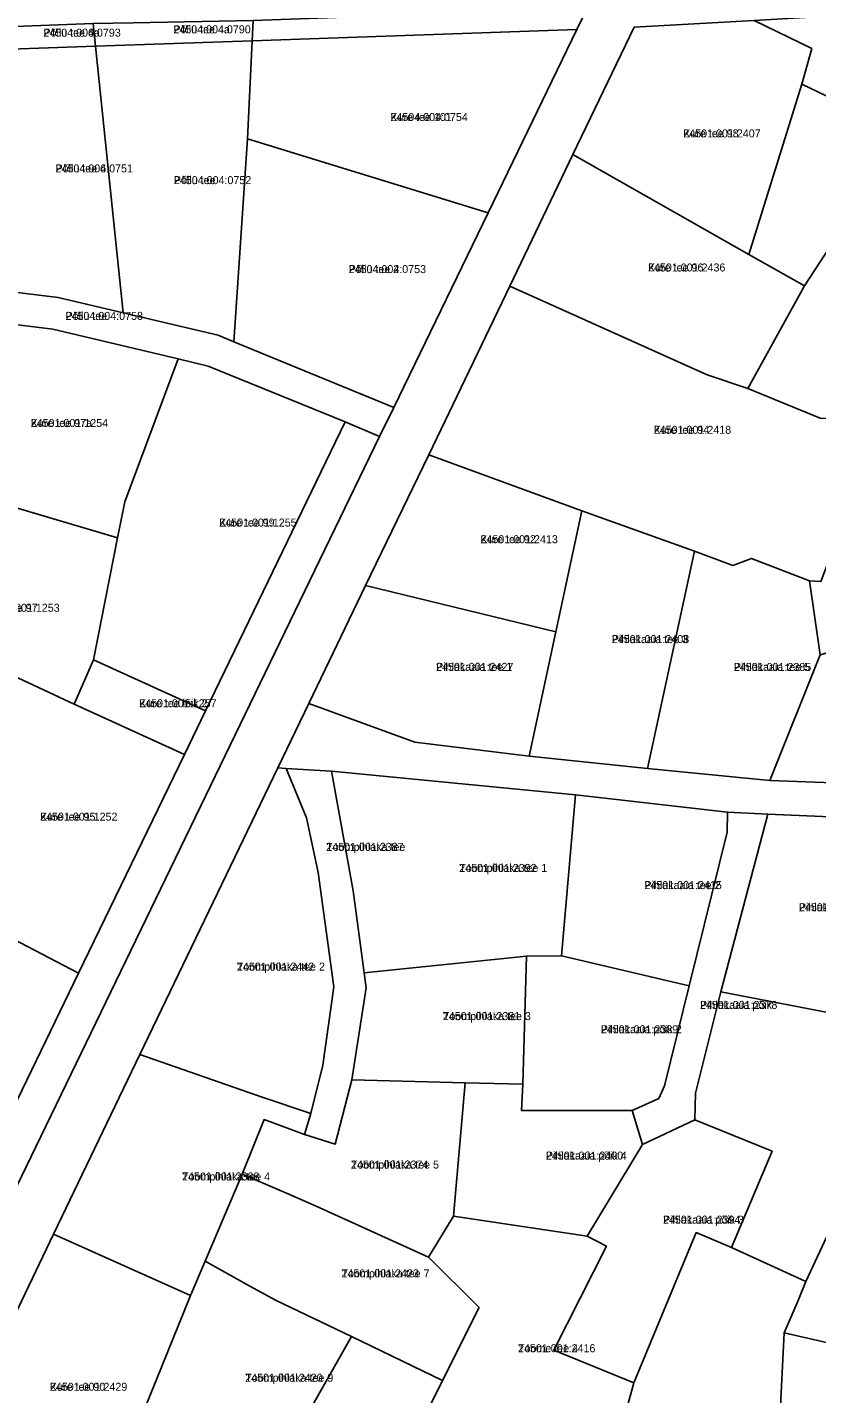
# Model space of a CAD drawing. Extents: x 551291 to 575799, y 6581704 to 6610137.
# Drawn here: x 559378.6 to 559526.5, y 6593957.3 to 6594213.3 of the extents above; entities that cross this region are included whole.
import ezdxf

# ---------------------------------------------------------------- set-up
doc = ezdxf.new("R2010")
doc.units = 0
for name, color, linetype in [('L_AADRESS', 7, 'Continuous'), ('PIIR', 7, 'Continuous'), ('TUNNUS', 7, 'Continuous')]:
    doc.layers.add(name, color=color, linetype=linetype)

msp = doc.modelspace()

# ---------------------------------------------------------------- linework, layer by layer
at = {"layer": 'PIIR'}
for points in [[(559525.57, 6594209.38), (559514.78, 6594214.62), (559615.8, 6594220.58), (559594.25, 6594191.44), (559591.29, 6594190.7), (559546.62, 6594191.67), (559523.72, 6594202.7)], [(559420.86, 6594214.59), (559436.5, 6594215.15), (559458.66, 6594216.29), (559484.05, 6594218.05), (559481.53, 6594212.94), (559420.69, 6594210.82)], [(559372.03, 6594213.32), (559377.81, 6594213.53), (559390.9, 6594214.04), (559391.34, 6594209.8), (559371.86, 6594209.12)], [(559390.9, 6594214.04), (559398.4, 6594214.15), (559420.86, 6594214.59), (559420.69, 6594210.82), (559391.34, 6594209.8)], [(559420.69, 6594210.82), (559481.53, 6594212.94), (559464.89, 6594178.58), (559419.83, 6594192.43)], [(559480.81, 6594189.47), (559492.26, 6594213.33), (559514.78, 6594214.62), (559525.57, 6594209.38), (559523.72, 6594202.7), (559513.75, 6594170.78)], [(559391.34, 6594209.8), (559420.69, 6594210.82), (559419.83, 6594192.43), (559417.25, 6594154.4), (559414.29, 6594155.61), (559396.5, 6594159.81)], [(559371.86, 6594209.12), (559391.34, 6594209.8), (559396.5, 6594159.81), (559384.32, 6594162.68), (559372.02, 6594164.2), (559371.19, 6594193.81)], [(559513.75, 6594170.78), (559523.72, 6594202.7), (559546.62, 6594191.67), (559541.73, 6594185.64), (559538.41, 6594186.65), (559524.21, 6594164.88)], [(559419.83, 6594192.43), (559464.89, 6594178.58), (559447.22, 6594142.1), (559417.25, 6594154.4)], [(559468.99, 6594164.84), (559480.81, 6594189.47), (559513.75, 6594170.78), (559524.21, 6594164.88), (559513.56, 6594145.66), (559505.93, 6594148.22)], [(559524.21, 6594164.88), (559538.41, 6594186.65), (559541.73, 6594185.64), (559554.94, 6594185.57), (559551.76, 6594178.32), (559545, 6594161.31), (559542.31, 6594157.52), (559540, 6594152.04), (559536.9, 6594139.9), (559527.11, 6594140.11), (559513.56, 6594145.66)], [(559453.77, 6594133.23), (559468.99, 6594164.84), (559505.93, 6594148.22), (559513.56, 6594145.66), (559527.11, 6594140.11), (559536.9, 6594139.9), (559533.88, 6594127.02), (559531.45, 6594120.4), (559527.29, 6594109.45), (559525.12, 6594109.62), (559514.29, 6594113.8), (559510.75, 6594112.49), (559503.57, 6594115.15), (559482.5, 6594122.71)], [(559353.48, 6594130.09), (559363.55, 6594159.21), (559383.32, 6594156.78), (559406.79, 6594151.23), (559396.8, 6594124.4), (559395.42, 6594117.64)], [(559396.8, 6594124.4), (559406.79, 6594151.23), (559412.44, 6594149.82), (559438.12, 6594139.38), (559411.94, 6594085.21), (559390.93, 6594094.77), (559395.42, 6594117.64)], [(559171.21, 6593753.59), (559201.87, 6593775.34), (559209.55, 6593780.73), (559246.25, 6593806.94), (559271.02, 6593824.58), (559293.51, 6593840.52), (559316.24, 6593887.55), (559335.18, 6593926.77), (559358.82, 6593975.74), (559369.18, 6593996.97), (559372.27, 6594003.33), (559388.13, 6594036.07), (559408, 6594077.05), (559411.94, 6594085.21), (559438.12, 6594139.38), (559444.58, 6594136.67), (559299.06, 6593836.09), (559146.17, 6593723.99), (559138.1, 6593729.93)], [(559441.92, 6594108.7), (559453.77, 6594133.23), (559482.5, 6594122.71), (559477.61, 6594100.06)], [(559347.84, 6594112.65), (559353.48, 6594130.09), (559395.42, 6594117.64), (559390.93, 6594094.77), (559387.35, 6594086.49), (559374.9, 6594092.31), (559366.72, 6594077.52), (559341.33, 6594091.68), (559351.27, 6594111.15)], [(559531.45, 6594120.4), (559533.88, 6594127.02), (559555.26, 6594117.08), (559554.81, 6594116.14), (559561.17, 6594103.3), (559552.29, 6594101.8), (559549.96, 6594102.04), (559527.12, 6594095.71), (559525.12, 6594109.62), (559527.29, 6594109.45)], [(559477.61, 6594100.06), (559482.5, 6594122.71), (559503.57, 6594115.15), (559494.8, 6594074.46), (559472.62, 6594076.76)], [(559494.8, 6594074.46), (559503.57, 6594115.15), (559510.75, 6594112.49), (559514.29, 6594113.8), (559525.12, 6594109.62), (559527.12, 6594095.71), (559517.71, 6594072.17)], [(559431.33, 6594086.6), (559441.92, 6594108.7), (559477.61, 6594100.06), (559472.62, 6594076.76), (559451.2, 6594079.35)], [(559517.71, 6594072.17), (559527.12, 6594095.71), (559549.96, 6594102.04), (559552.29, 6594101.8), (559561.17, 6594103.3), (559576.1, 6594072.98), (559576.14, 6594071.72), (559541.24, 6594071.33)], [(559408, 6594077.05), (559387.35, 6594086.49), (559390.93, 6594094.77), (559411.94, 6594085.21)], [(559366.72, 6594077.52), (559374.9, 6594092.31), (559387.35, 6594086.49), (559408, 6594077.05), (559388.13, 6594036.07), (559353.88, 6594053.95), (559357.52, 6594060.57)], [(559399.64, 6594020.83), (559425.5, 6594074.54), (559427.08, 6594074.4), (559430.89, 6594065.16), (559433.07, 6594054.94), (559436, 6594033.5), (559433.92, 6594018.82), (559431.66, 6594009.79), (559422.56, 6594012.86)], [(559430.89, 6594065.16), (559427.08, 6594074.4), (559435.54, 6594073.94), (559439.59, 6594051.52), (559441.68, 6594036.16), (559442.05, 6594033.3), (559439.34, 6594016.06), (559436.27, 6594004.06), (559430.49, 6594005.86), (559431.66, 6594009.79), (559433.92, 6594018.82), (559436, 6594033.5), (559433.07, 6594054.94)], [(559439.59, 6594051.52), (559435.54, 6594073.94), (559481.29, 6594069.48), (559478.65, 6594039.31), (559472.08, 6594039.28), (559441.68, 6594036.16)], [(559478.65, 6594039.31), (559481.29, 6594069.48), (559509.76, 6594066.22), (559509.69, 6594062.52), (559502.59, 6594033.7)], [(559509.69, 6594062.52), (559509.76, 6594066.22), (559517.34, 6594065.86), (559508.5, 6594032.57), (559503.8, 6594013.56), (559503.67, 6594008.61), (559493.84, 6594003.98), (559491.88, 6594010.31), (559496.88, 6594012.57), (559497.95, 6594014.95), (559502.59, 6594033.7)], [(559508.5, 6594032.57), (559517.34, 6594065.86), (559537.81, 6594065.01), (559532.45, 6594027.95)], [(559357.07, 6594012.9), (559338.17, 6594024.81), (559343.93, 6594035.56), (559350.52, 6594047.77), (559353.88, 6594053.95), (559388.13, 6594036.07), (559372.27, 6594003.33)], [(559442.05, 6594033.3), (559441.68, 6594036.16), (559472.08, 6594039.28), (559471.39, 6594015.28), (559460.58, 6594015.5), (559439.34, 6594016.06)], [(559471.39, 6594015.28), (559472.08, 6594039.28), (559478.65, 6594039.31), (559502.59, 6594033.7), (559497.95, 6594014.95), (559496.88, 6594012.57), (559491.88, 6594010.31), (559471.17, 6594010.31)], [(559503.8, 6594013.56), (559508.5, 6594032.57), (559532.45, 6594027.95), (559532.61, 6594026.5), (559549.59, 6594018.25), (559542.97, 6594005.83), (559539.06, 6594007.96), (559531.43, 6593993.29), (559524.48, 6593978.3), (559510.5, 6593984.68), (559518.14, 6594002.71), (559503.67, 6594008.61)], [(559383.45, 6593987.17), (559399.64, 6594020.83), (559422.56, 6594012.86), (559431.66, 6594009.79), (559430.49, 6594005.86), (559422.91, 6594008.65), (559418.81, 6593998.4), (559411.9, 6593982.1), (559409.15, 6593975.66)], [(559436.27, 6594004.06), (559439.34, 6594016.06), (559460.58, 6594015.5), (559458.39, 6593990.56), (559453.74, 6593982.85), (559432.66, 6593992.4), (559427.15, 6593994.88), (559418.81, 6593998.4), (559422.91, 6594008.65), (559430.49, 6594005.86)], [(559458.39, 6593990.56), (559460.58, 6594015.5), (559471.39, 6594015.28), (559471.17, 6594010.31), (559491.88, 6594010.31), (559493.84, 6594003.98), (559483.44, 6593986.78)], [(559483.44, 6593986.78), (559493.84, 6594003.98), (559503.67, 6594008.61), (559518.14, 6594002.71), (559510.5, 6593984.68), (559503.91, 6593987.47), (559492.2, 6593959.32), (559477.21, 6593965.41), (559487.09, 6593984.93)], [(559411.9, 6593982.1), (559418.81, 6593998.4), (559427.15, 6593994.88), (559432.66, 6593992.4), (559453.74, 6593982.85), (559463.21, 6593973.42), (559456.34, 6593959.73), (559439.32, 6593967.96), (559425.04, 6593974.79), (559419.69, 6593977.74)], [(559524.48, 6593978.3), (559531.43, 6593993.29), (559547.14, 6593984.63), (559550.59, 6593991.01), (559551.21, 6593990.48), (559556.52, 6593987.57), (559552.3, 6593978.21), (559547.7, 6593962.42), (559520.38, 6593968.65), (559522.99, 6593974.73)], [(559453.74, 6593982.85), (559458.39, 6593990.56), (559483.44, 6593986.78), (559487.09, 6593984.93), (559477.21, 6593965.41), (559492.2, 6593959.32), (559488.25, 6593944.93), (559475.84, 6593951.42), (559468.67, 6593937.86), (559455.2, 6593943.41), (559454.33, 6593941.91), (559448.82, 6593944.59), (559456.34, 6593959.73), (559463.21, 6593973.42)], [(559356.41, 6593930.63), (559383.45, 6593987.17), (559409.15, 6593975.66), (559399.46, 6593951.77), (559396.72, 6593952.85), (559384.6, 6593929.42), (559377.88, 6593931.06), (559371.31, 6593922.02)], [(559484.28, 6593928.76), (559488.25, 6593944.93), (559492.2, 6593959.32), (559503.91, 6593987.47), (559510.5, 6593984.68), (559524.48, 6593978.3), (559522.99, 6593974.73), (559520.38, 6593968.65), (559517.17, 6593903.73), (559486.64, 6593900.44), (559490.65, 6593927.02)], [(559409.15, 6593975.66), (559411.9, 6593982.1), (559419.69, 6593977.74), (559425.04, 6593974.79), (559439.32, 6593967.96), (559422.99, 6593939.22), (559407.09, 6593947.55), (559399.46, 6593951.77)], [(559422.99, 6593939.22), (559439.32, 6593967.96), (559456.34, 6593959.73), (559448.82, 6593944.59), (559437.59, 6593918.27), (559417.92, 6593930.65)], [(559517.17, 6593903.73), (559520.38, 6593968.65), (559547.7, 6593962.42), (559544.62, 6593948.45), (559541.76, 6593948.19), (559533.53, 6593905.49)]]:
    msp.add_lwpolyline(points, close=True, dxfattribs=at)
for points in [[(558177.52, 6592770.55), (558170.99, 6592891.67), (558187.73, 6592959.33), (558210.3, 6593010.98), (558251.88, 6593067.47), (558331.23, 6593148.23), (558500.98, 6593273.8), (558515.98, 6593265.59), (558725.44, 6593417.8), (558892.15, 6593539.14), (558974.44, 6593599.03), (559131.4, 6593713.23), (559146.17, 6593723.99), (559299.06, 6593836.09), (559444.58, 6594136.67), (559447.22, 6594142.1), (559464.89, 6594178.58), (559481.53, 6594212.94), (559484.05, 6594218.05)], [(559492.26, 6594213.33), (559480.81, 6594189.47), (559468.99, 6594164.84), (559453.77, 6594133.23), (559441.92, 6594108.7), (559431.33, 6594086.6), (559425.5, 6594074.54), (559399.64, 6594020.83), (559383.45, 6593987.17), (559356.41, 6593930.63), (559317.89, 6593848.3), (559321.54, 6593844.35), (559395.22, 6593879.55), (559395, 6593880.5), (559407.84, 6593886.81), (559427.42, 6593891.23), (559444.52, 6593895.06), (559451.86, 6593896.71), (559469.1, 6593898.55), (559486.64, 6593900.44), (559517.17, 6593903.73), (559533.53, 6593905.49)], [(559372.02, 6594164.2), (559384.32, 6594162.68), (559396.5, 6594159.81), (559414.29, 6594155.61), (559417.25, 6594154.4), (559447.22, 6594142.1), (559444.58, 6594136.67), (559438.12, 6594139.38), (559412.44, 6594149.82), (559406.79, 6594151.23), (559383.32, 6594156.78), (559363.55, 6594159.21)], [(559537.81, 6594065.01), (559517.34, 6594065.86), (559509.76, 6594066.22), (559481.29, 6594069.48), (559435.54, 6594073.94), (559427.08, 6594074.4), (559425.5, 6594074.54), (559431.33, 6594086.6), (559451.2, 6594079.35), (559472.62, 6594076.76), (559494.8, 6594074.46), (559517.71, 6594072.17), (559541.24, 6594071.33)]]:
    msp.add_lwpolyline(points, dxfattribs=at)

# ---------------------------------------------------------------- texts
at = {"layer": 'L_AADRESS'}
for s, p in [('Põllu tee 6a', (559381.56, 6594211.58)), ('Põllu tee 4a', (559405.92, 6594212.2)), ('Kure tee 101', (559446.6, 6594195.76)), ('Kure tee 98', (559501.48, 6594192.7)), ('Põllu tee 6', (559383.84, 6594186.14)), ('Põllu tee 4', (559406.02, 6594183.94)), ('Põllu tee 2', (559438.77, 6594167.27)), ('Kure tee 96', (559494.87, 6594167.57)), ('Põllu tee', (559385.72, 6594158.5)), ('Kure tee 97a', (559379.19, 6594138.43)), ('Kure tee 94', (559495.95, 6594137.15)), ('Kure tee 99', (559414.52, 6594119.77)), ('Kure tee 92', (559463.47, 6594116.65)), ('Kure tee 97', (559370.11, 6594103.8)), ('Pihlakaaia tee 3', (559488.09, 6594097.93)), ('Pihlakaaia tee 1', (559455.15, 6594092.73)), ('Pihlakaaia tee 5', (559510.96, 6594092.71)), ('Kure tee lõik 2', (559399.51, 6594085.91)), ('Kure tee 95', (559380.94, 6594064.65)), ('Toompihlaka tee', (559434.56, 6594059)), ('Toompihlaka tee 1', (559459.49, 6594055.05)), ('Pihlakaaia tee 2', (559494.2, 6594051.83)), ('Pihlakaaia tee 4', (559523.16, 6594047.68)), ('Toompihlaka tee 2', (559417.82, 6594036.55)), ('Pihlakaaia põik', (559504.61, 6594029.37)), ('Toompihlaka tee 3', (559456.42, 6594027.28)), ('Pihlakaaia põik 2', (559486.03, 6594024.81)), ('Pihlakaaia põik 4', (559475.72, 6594001.14)), ('Toompihlaka tee 5', (559439.2, 6593999.46)), ('Toompihlaka tee 4', (559407.55, 6593997.23)), ('Pihlakaaia põik 3', (559497.68, 6593989.13)), ('Toompihlaka tee 7', (559437.43, 6593979.07)), ('Toome tee 4', (559470.51, 6593965.04)), ('Kure tee 90', (559382.78, 6593957.82)), ('Toompihlaka tee 9', (559419.39, 6593959.51))]:
    msp.add_text(s, height=1.5, dxfattribs=at).set_placement(p)
at = {"layer": 'TUNNUS'}
for s, p in [('24504:004:0793', (559381.56, 6594211.58)), ('24504:004:0790', (559405.92, 6594212.2)), ('24504:004:0754', (559446.6, 6594195.76)), ('24501:001:2407', (559501.48, 6594192.7)), ('24504:004:0751', (559383.84, 6594186.14)), ('24504:004:0752', (559406.02, 6594183.94)), ('24501:001:2436', (559494.87, 6594167.57)), ('24504:004:0753', (559438.77, 6594167.27)), ('24504:004:0758', (559385.72, 6594158.5)), ('24501:001:1254', (559379.19, 6594138.43)), ('24501:001:2418', (559495.95, 6594137.15)), ('24501:001:1255', (559414.52, 6594119.77)), ('24501:001:2413', (559463.47, 6594116.65)), ('24501:001:1253', (559370.11, 6594103.8)), ('24501:001:2408', (559488.09, 6594097.93)), ('24501:001:2427', (559455.15, 6594092.73)), ('24501:001:2385', (559510.96, 6594092.71)), ('24501:001:1257', (559399.51, 6594085.91)), ('24501:001:1252', (559380.94, 6594064.65)), ('24501:001:2387', (559434.56, 6594059)), ('24501:001:2392', (559459.49, 6594055.05)), ('24501:001:2415', (559494.2, 6594051.83)), ('24501:001:2386', (559523.16, 6594047.68)), ('24501:001:2442', (559417.82, 6594036.55)), ('24501:001:2378', (559504.61, 6594029.37)), ('24501:001:2381', (559456.42, 6594027.28)), ('24501:001:2389', (559486.03, 6594024.81)), ('24501:001:2400', (559475.72, 6594001.14)), ('24501:001:2374', (559439.2, 6593999.46)), ('24501:001:2388', (559407.55, 6593997.23)), ('24501:001:2394', (559497.68, 6593989.13)), ('24501:001:2423', (559437.43, 6593979.07)), ('24501:001:2416', (559470.51, 6593965.04)), ('24501:001:2429', (559382.78, 6593957.82)), ('24501:001:2420', (559419.39, 6593959.51))]:
    msp.add_text(s, height=1.5, dxfattribs=at).set_placement(p)

doc.saveas('drawing.dxf')
